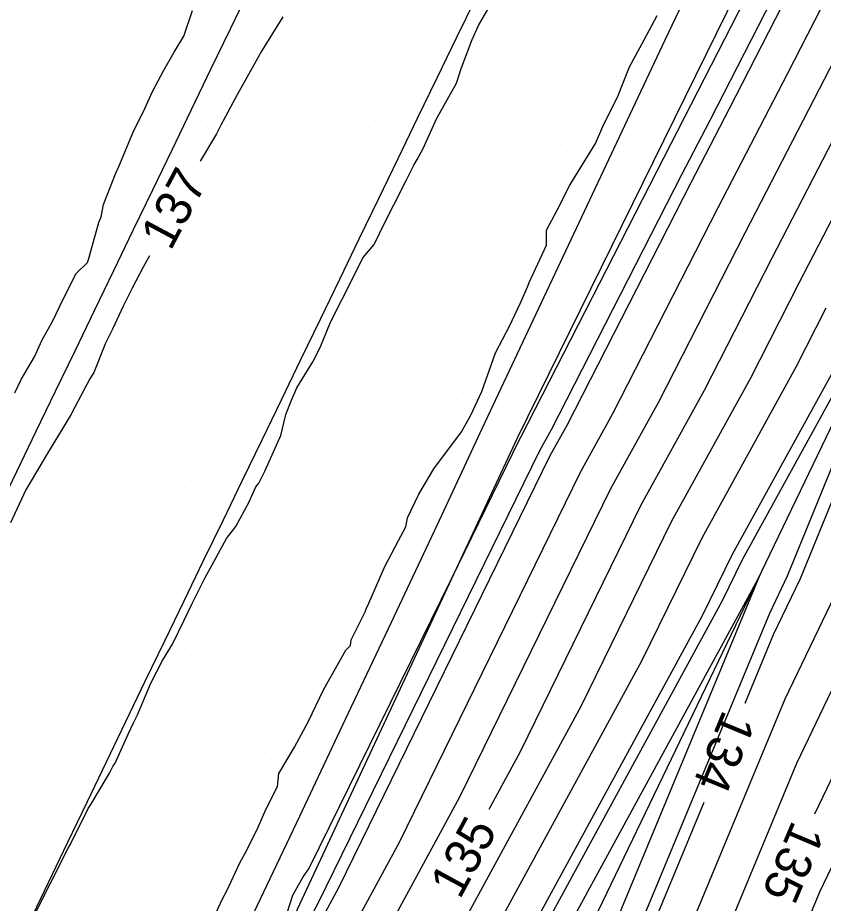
# Model space of a CAD drawing. Extents: x 2354170 to 2357230, y 866100 to 868290.
# Drawn here: x 2355293.68 to 2355338.78, y 866360.82 to 866410.37 of the extents above; entities that cross this region are included whole.
import ezdxf

# ---------------------------------------------------------------- set-up
doc = ezdxf.new("R2010")
doc.units = 0
for name, color, linetype in [('Default', 7, 'Continuous'), ('DTM Contours Major', 7, 'Continuous'), ('DTM Contours Major Text', 7, 'Continuous'), ('DTM Contours Minor', 7, 'Continuous'), ('DTM Contours Minor Text', 7, 'Continuous'), ('Exist DTM Breakline', 7, 'Continuous'), ('Exist DTM Scan Elevation Point', 7, 'Continuous'), ('Exist Roads EOP', 7, 'Continuous'), ('PH Exist DTM Breakline', 7, 'Continuous')]:
    doc.layers.add(name, color=color, linetype=linetype)

msp = doc.modelspace()

# ---------------------------------------------------------------- linework, layer by layer
at = {"layer": 'Default'}
for points in [[(2355334.401, 866372.018), (2355335.993, 866375.854), (2355337.498, 866378.987), (2355342.253, 866390.626), (2355343.246, 866392.695), (2355356.16, 866417.149), (2355356.262, 866417.357), (2355362.221, 866428.642), (2355363.371, 866431), (2355375.289, 866455.784), (2355376.359, 866457.979), (2355378.218, 866461.844)], [(2355338.298, 866365.818), (2355343.993, 866377.674), (2355346.753, 866384.429), (2355352.692, 866396.81), (2355360.315, 866411.244), (2355360.872, 866412.387), (2355364.386, 866419.041), (2355370.481, 866431.549), (2355377.431, 866446.002), (2355382.14, 866455.663)], [(2355365.278, 866455.25), (2355363.145, 866450.833), (2355355.882, 866436.056), (2355353.134, 866430.365), (2355349.614, 866423.554), (2355343.286, 866411.203), (2355335.903, 866396.918), (2355332.11, 866389.513), (2355328.572, 866383.089), (2355321.813, 866369.29), (2355320.06, 866366.07)], [(2355362.019, 866434.7), (2355360.618, 866431.85), (2355360.1, 866430.777), (2355354.214, 866419.388), (2355353.064, 866417.142), (2355340.439, 866392.713), (2355339.805, 866391.476), (2355333.667, 866380.332), (2355331.988, 866376.904), (2355319.48, 866353.942), (2355315.349, 866346.27)], [(2355308.598, 866359.764), (2355309.085, 866361.27), (2355309.657, 866362.299), (2355309.98, 866362.752), (2355317.96, 866378.969), (2355321.778, 866386.765), (2355321.85, 866386.896), (2355329.855, 866402.524), (2355330.249, 866403.286), (2355343.48, 866429.109)], [(2355344.863, 866427.426), (2355333.508, 866405.265), (2355331.367, 866401.122), (2355324.415, 866387.55), (2355323.476, 866385.846), (2355311.639, 866361.675), (2355310.176, 866358.99), (2355309.668, 866358.047), (2355299.946, 866338.09)], [(2355346.547, 866426.331), (2355336.768, 866407.245), (2355332.879, 866399.721), (2355326.98, 866388.205), (2355325.175, 866384.927), (2355315.03, 866364.214), (2355311.726, 866358.149), (2355310.58, 866356.02), (2355301.98, 866338.364), (2355299.636, 866333.974), (2355288.647, 866311.443), (2355286.904, 866307.449), (2355279.659, 866292.572), (2355279.343, 866291.067), (2355277.379, 866286.427), (2355269.582, 866267.361)], [(2355346.545, 866413.183), (2355337.415, 866395.516), (2355334.675, 866390.167), (2355330.27, 866382.17), (2355325.205, 866371.828), (2355316.378, 866355.625), (2355313.316, 866349.936), (2355308.274, 866339.587), (2355301.426, 866326.76), (2355294.428, 866312.41), (2355289.665, 866301.5), (2355285.05, 866292.025), (2355284.22, 866288.074), (2355279.066, 866275.895)], [(2355294.374, 866359.67), (2355295.392, 866361.693), (2355295.504, 866361.898), (2355296.511, 866363.894), (2355296.633, 866364.125), (2355297.628, 866366.123), (2355297.78, 866366.343), (2355298.816, 866368.103), (2355299.029, 866368.505), (2355299.143, 866368.656), (2355299.861, 866370.272), (2355300.162, 866370.917), (2355300.381, 866371.358), (2355301.13, 866373.134), (2355301.79, 866374.396), (2355302.344, 866375.317), (2355303.004, 866376.664), (2355303.437, 866377.546), (2355304.185, 866379.056), (2355304.573, 866379.763), (2355305.375, 866381.228), (2355305.901, 866381.896), (2355306.612, 866383.249), (2355307.008, 866384.127), (2355307.173, 866384.327), (2355307.513, 866385.005), (2355308.249, 866386.613), (2355308.412, 866386.992), (2355308.701, 866388.165), (2355309.011, 866388.966), (2355309.317, 866389.651), (2355310.198, 866391.115), (2355310.608, 866391.924), (2355311.193, 866393.331), (2355311.825, 866394.578), (2355312.303, 866395.542), (2355313.006, 866396.927), (2355313.629, 866397.687), (2355314.258, 866398.939), (2355314.744, 866399.903), (2355315.423, 866401.255), (2355315.853, 866402.126), (2355316.039, 866402.442), (2355316.386, 866403.048), (2355317.13, 866404.718), (2355318.242, 866406.714), (2355318.322, 866406.927), (2355318.482, 866407.479), (2355319.114, 866409.148), (2355319.475, 866409.933), (2355320.277, 866411.31)], [(2355304.299, 866359.25), (2355305.15, 866361.071), (2355305.394, 866361.523), (2355306.122, 866363.073), (2355306.501, 866363.789), (2355307.139, 866365.084), (2355307.576, 866366.075), (2355308.219, 866367.347), (2355308.292, 866368.085), (2355309.184, 866369.551), (2355309.941, 866370.98), (2355310.826, 866372.806), (2355312.05, 866374.99), (2355312.307, 866375.25), (2355312.345, 866375.55), (2355313.135, 866377.13), (2355313.209, 866377.336), (2355313.346, 866377.603), (2355314.23, 866379.658), (2355315, 866381.118), (2355315.41, 866381.875), (2355315.511, 866382.39), (2355316.142, 866383.704), (2355316.969, 866385.118), (2355318.531, 866387.205), (2355319.046, 866388.125), (2355319.659, 866389.453), (2355320.433, 866391.623), (2355321.216, 866393.109), (2355321.829, 866394.415), (2355322.23, 866395.349), (2355322.319, 866395.551), (2355323.286, 866397.648), (2355323.274, 866398.489), (2355323.881, 866399.608), (2355324.586, 866400.992), (2355326.024, 866403.328), (2355326.495, 866404.411), (2355327.25, 866405.927), (2355327.928, 866407.61), (2355328.749, 866409.137), (2355329.472, 866410.499)], [(2355340.027, 866409.224), (2355334.391, 866398.319), (2355329.545, 866388.859), (2355326.873, 866384.008), (2355318.422, 866366.752), (2355313.277, 866357.307), (2355311.492, 866353.992), (2355304.078, 866338.772), (2355300.233, 866331.569), (2355290.574, 866311.765), (2355287.824, 866305.466), (2355281.456, 866292.39), (2355280.968, 866290.07), (2355277.941, 866282.916), (2355271.317, 866266.718)], [(2355338.927, 866394.115), (2355337.24, 866390.821), (2355331.969, 866381.251), (2355328.597, 866374.366), (2355317.929, 866354.783), (2355314.227, 866347.909), (2355310.373, 866339.995), (2355302.023, 866324.355), (2355296.354, 866312.732), (2355290.585, 866299.517), (2355286.848, 866291.842), (2355285.846, 866287.077), (2355279.628, 866272.384)], [(2355307.474, 866311.114), (2355309.825, 866316.293), (2355318.648, 866338.833), (2355320.345, 866342.59), (2355324.053, 866352.236), (2355335.221, 866379.152), (2355321.03, 866353.1), (2355316.051, 866343.853), (2355314.569, 866340.81), (2355303.217, 866319.546), (2355300.208, 866313.377), (2355292.425, 866295.55), (2355290.442, 866291.477), (2355289.097, 866285.082), (2355280.753, 866265.362)], [(2355295.93, 866277.918), (2355297.289, 866281.095), (2355299.682, 866284.596), (2355304.457, 866295.671), (2355310.044, 866308.469), (2355314.474, 866318.226), (2355320.982, 866334.853), (2355325.394, 866344.623), (2355328.175, 866351.855), (2355336.64, 866372.256), (2355339.663, 866378.549)], [(2355297.265, 866276.227), (2355299.022, 866280.337), (2355300.896, 866283.079), (2355306.792, 866296.752), (2355311.329, 866307.146), (2355316.798, 866319.192), (2355322.15, 866332.863), (2355327.919, 866345.64), (2355330.235, 866351.664), (2355337.287, 866368.659), (2355341.828, 866378.112)], [(2355299.933, 866272.846), (2355302.488, 866278.82), (2355303.324, 866280.044), (2355311.461, 866298.914), (2355313.9, 866304.5), (2355321.447, 866321.125), (2355324.484, 866328.882), (2355332.969, 866347.673), (2355334.356, 866351.282), (2355338.581, 866361.464), (2355346.158, 866377.236)], [(2355291.94, 866275.064), (2355294.596, 866279.608), (2355295.556, 866281.853), (2355298.468, 866286.114), (2355302.123, 866294.59), (2355308.759, 866309.791), (2355312.149, 866317.259), (2355319.815, 866336.843), (2355322.869, 866343.607), (2355326.114, 866352.046), (2355332.101, 866366.476)]]:
    msp.add_lwpolyline(points, dxfattribs=at)
at = {"layer": 'DTM Contours Major'}
for points in [[(2355338.298, 866365.818), (2355343.993, 866377.674), (2355346.753, 866384.429), (2355352.692, 866396.81), (2355360.315, 866411.244), (2355360.872, 866412.387), (2355364.386, 866419.041), (2355370.481, 866431.549), (2355377.431, 866446.002), (2355382.14, 866455.663)], [(2355365.278, 866455.25), (2355363.145, 866450.833), (2355355.882, 866436.056), (2355353.134, 866430.365), (2355349.614, 866423.554), (2355343.286, 866411.203), (2355335.903, 866396.918), (2355332.11, 866389.513), (2355328.572, 866383.089), (2355321.813, 866369.29), (2355320.06, 866366.07)]]:
    msp.add_lwpolyline(points, dxfattribs=at)
at = {"layer": 'DTM Contours Minor'}
for points in [[(2355399.763, 866516.766), (2355393.392, 866501.457), (2355392.787, 866500.397), (2355391.502, 866497.306), (2355381.19, 866472.262), (2355380.988, 866471.775), (2355374.355, 866458.281), (2355373.867, 866457.271), (2355361.144, 866431.383), (2355360.874, 866430.823), (2355354.726, 866418.925), (2355354.15, 866417.801), (2355340.943, 866392.246), (2355340.66, 866391.694), (2355334.233, 866380.026), (2355333.119, 866377.75), (2355319.997, 866353.661), (2355315.443, 866345.205), (2355313.17, 866340.539), (2355311.526, 866337.459)], [(2355308.331, 866310.232), (2355311.374, 866316.937), (2355319.426, 866337.506), (2355322.028, 866343.268), (2355325.427, 866352.109), (2355335.777, 866377.053), (2355336.776, 866379.133), (2355341.753, 866391.314), (2355342.196, 866392.238), (2355355.699, 866417.805), (2355355.75, 866417.909), (2355361.981, 866429.708), (2355362.581, 866430.939), (2355375.051, 866456.87), (2355375.559, 866457.912), (2355382.058, 866471.427), (2355382.481, 866472.365), (2355392.371, 866491.519)], [(2355267.268, 866268.217), (2355276.63, 866291.108), (2355277.175, 866292.398), (2355277.263, 866292.816), (2355285.677, 866310.094), (2355286.078, 866311.013), (2355298.84, 866337.18), (2355299.182, 866337.821), (2355309.364, 866358.723), (2355309.659, 866359.271), (2355310.508, 866360.829), (2355322.91, 866386.152), (2355323.56, 866387.332), (2355330.863, 866401.589), (2355332.422, 866404.606), (2355337.089, 866413.714)], [(2355293.531, 866389.374), (2355293.872, 866390.129), (2355294.621, 866391.4), (2355295.047, 866392.35), (2355295.647, 866393.413), (2355296.201, 866394.584), (2355296.959, 866396.058), (2355297.588, 866396.664), (2355297.645, 866396.841), (2355298.231, 866398.901), (2355298.349, 866399.221), (2355298.495, 866399.923), (2355299.153, 866401.624), (2355299.349, 866402.042), (2355300.148, 866403.963), (2355300.806, 866405.288), (2355301.23, 866406.245), (2355301.86, 866407.426), (2355302.433, 866408.446), (2355302.979, 866409.338), (2355303.46, 866410.764)], [(2355308.518, 866410.416), (2355307.277, 866408.409), (2355307.21, 866408.284), (2355307.129, 866408.13), (2355305.995, 866406.089), (2355305.061, 866404.35), (2355304.81, 866403.876), (2355303.891, 866402.338)], [(2355301.065, 866397.048), (2355300.712, 866396.403), (2355300.098, 866395.24), (2355299.602, 866394.259), (2355298.985, 866392.939), (2355298.602, 866392.164), (2355297.945, 866390.522), (2355297.724, 866390.165), (2355296.722, 866388.262), (2355296.676, 866388.188), (2355296.234, 866387.445), (2355295.445, 866386.155), (2355295.418, 866386.109), (2355295.388, 866386.054), (2355294.137, 866383.959), (2355293.278, 866382.106)]]:
    msp.add_lwpolyline(points, dxfattribs=at)
at = {"layer": 'Exist DTM Breakline'}
for points in [[(2355281.733, 866360.182), (2355282.807, 866362.44), (2355283.88, 866364.698), (2355284.954, 866366.955), (2355286.027, 866369.213), (2355287.104, 866371.469), (2355288.192, 866373.72), (2355289.279, 866375.971), (2355290.367, 866378.223), (2355291.454, 866380.474), (2355292.542, 866382.725), (2355293.629, 866384.976), (2355294.717, 866387.227), (2355295.804, 866389.478), (2355296.892, 866391.729), (2355297.979, 866393.98), (2355299.067, 866396.231), (2355300.154, 866398.482), (2355301.242, 866400.733), (2355302.329, 866402.984), (2355303.416, 866405.236), (2355304.501, 866407.488), (2355305.586, 866409.74), (2355306.671, 866411.993)], [(2355319.318, 866411.481), (2355318.23, 866409.23), (2355317.141, 866406.979), (2355316.052, 866404.729), (2355314.963, 866402.479), (2355313.874, 866400.228), (2355312.785, 866397.978), (2355311.696, 866395.728), (2355310.607, 866393.477), (2355309.518, 866391.227), (2355308.43, 866388.976), (2355307.342, 866386.725), (2355306.253, 866384.475), (2355305.164, 866382.225), (2355304.073, 866379.975), (2355302.982, 866377.726), (2355301.892, 866375.476), (2355300.806, 866373.224), (2355299.723, 866370.971), (2355298.64, 866368.718), (2355297.557, 866366.465), (2355296.471, 866364.212), (2355295.385, 866361.961), (2355294.298, 866359.709)]]:
    msp.add_lwpolyline(points, dxfattribs=at)
at = {"layer": 'Exist DTM Scan Elevation Point'}
for p, q in [((2355295.981, 866409.717), (2355295.981, 866409.717)), ((2355304.995, 866409.749), (2355304.995, 866409.749)), ((2355314.009, 866409.781), (2355314.009, 866409.781)), ((2355323.023, 866409.812), (2355323.023, 866409.812)), ((2355301.531, 866409.043), (2355301.531, 866409.043)), ((2355310.545, 866409.075), (2355310.545, 866409.075)), ((2355319.558, 866409.107), (2355319.558, 866409.107)), ((2355328.572, 866409.138), (2355328.572, 866409.138)), ((2355298.066, 866408.338), (2355298.066, 866408.338)), ((2355307.08, 866408.369), (2355307.08, 866408.369)), ((2355316.094, 866408.401), (2355316.094, 866408.401)), ((2355325.108, 866408.433), (2355325.108, 866408.433)), ((2355294.602, 866407.632), (2355294.602, 866407.632)), ((2355303.616, 866407.664), (2355303.616, 866407.664)), ((2355312.63, 866407.696), (2355312.63, 866407.696)), ((2355321.643, 866407.727), (2355321.643, 866407.727)), ((2355300.151, 866406.958), (2355300.151, 866406.958)), ((2355309.165, 866406.99), (2355309.165, 866406.99)), ((2355318.179, 866407.022), (2355318.179, 866407.022)), ((2355327.193, 866407.053), (2355327.193, 866407.053)), ((2355296.687, 866406.253), (2355296.687, 866406.253)), ((2355305.701, 866406.284), (2355305.701, 866406.284)), ((2355314.715, 866406.316), (2355314.715, 866406.316)), ((2355323.728, 866406.348), (2355323.728, 866406.348)), ((2355302.236, 866405.579), (2355302.236, 866405.579)), ((2355311.25, 866405.611), (2355311.25, 866405.611)), ((2355320.264, 866405.642), (2355320.264, 866405.642)), ((2355325.813, 866404.968), (2355325.813, 866404.968)), ((2355298.772, 866404.873), (2355298.772, 866404.873)), ((2355307.786, 866404.905), (2355307.786, 866404.905)), ((2355316.8, 866404.937), (2355316.8, 866404.937)), ((2355295.307, 866404.168), (2355295.307, 866404.168)), ((2355304.321, 866404.2), (2355304.321, 866404.2)), ((2355313.335, 866404.231), (2355313.335, 866404.231)), ((2355322.349, 866404.263), (2355322.349, 866404.263)), ((2355300.857, 866403.494), (2355300.857, 866403.494)), ((2355309.871, 866403.526), (2355309.871, 866403.526)), ((2355318.885, 866403.557), (2355318.885, 866403.557)), ((2355297.392, 866402.788), (2355297.392, 866402.788)), ((2355306.406, 866402.82), (2355306.406, 866402.82)), ((2355315.42, 866402.852), (2355315.42, 866402.852)), ((2355324.434, 866402.883), (2355324.434, 866402.883)), ((2355293.928, 866402.083), (2355293.928, 866402.083)), ((2355302.942, 866402.115), (2355302.942, 866402.115)), ((2355311.956, 866402.146), (2355311.956, 866402.146)), ((2355320.97, 866402.178), (2355320.97, 866402.178)), ((2355299.477, 866401.409), (2355299.477, 866401.409)), ((2355308.491, 866401.441), (2355308.491, 866401.441)), ((2355317.505, 866401.472), (2355317.505, 866401.472)), ((2355296.013, 866400.703), (2355296.013, 866400.703)), ((2355305.027, 866400.735), (2355305.027, 866400.735)), ((2355314.041, 866400.767), (2355314.041, 866400.767)), ((2355323.055, 866400.798), (2355323.055, 866400.798)), ((2355301.562, 866400.03), (2355301.562, 866400.03)), ((2355310.576, 866400.061), (2355310.576, 866400.061)), ((2355319.59, 866400.093), (2355319.59, 866400.093)), ((2355298.098, 866399.324), (2355298.098, 866399.324)), ((2355307.112, 866399.356), (2355307.112, 866399.356)), ((2355316.126, 866399.387), (2355316.126, 866399.387)), ((2355294.634, 866398.618), (2355294.634, 866398.618)), ((2355303.647, 866398.65), (2355303.647, 866398.65)), ((2355312.661, 866398.682), (2355312.661, 866398.682)), ((2355321.675, 866398.713), (2355321.675, 866398.713)), ((2355300.183, 866397.945), (2355300.183, 866397.945)), ((2355309.197, 866397.976), (2355309.197, 866397.976)), ((2355318.211, 866398.008), (2355318.211, 866398.008)), ((2355296.719, 866397.239), (2355296.719, 866397.239)), ((2355305.732, 866397.271), (2355305.732, 866397.271)), ((2355314.746, 866397.302), (2355314.746, 866397.302)), ((2355323.76, 866397.334), (2355323.76, 866397.334)), ((2355302.268, 866396.565), (2355302.268, 866396.565)), ((2355311.282, 866396.597), (2355311.282, 866396.597)), ((2355320.296, 866396.628), (2355320.296, 866396.628)), ((2355298.804, 866395.86), (2355298.804, 866395.86)), ((2355307.817, 866395.891), (2355307.817, 866395.891)), ((2355316.831, 866395.923), (2355316.831, 866395.923)), ((2355295.339, 866395.154), (2355295.339, 866395.154)), ((2355304.353, 866395.186), (2355304.353, 866395.186)), ((2355313.367, 866395.217), (2355313.367, 866395.217)), ((2355322.381, 866395.249), (2355322.381, 866395.249)), ((2355300.889, 866394.48), (2355300.889, 866394.48)), ((2355309.902, 866394.512), (2355309.902, 866394.512)), ((2355318.916, 866394.543), (2355318.916, 866394.543)), ((2355297.424, 866393.775), (2355297.424, 866393.775)), ((2355306.438, 866393.806), (2355306.438, 866393.806)), ((2355315.452, 866393.838), (2355315.452, 866393.838)), ((2355302.974, 866393.101), (2355302.974, 866393.101)), ((2355311.987, 866393.132), (2355311.987, 866393.132)), ((2355321.001, 866393.164), (2355321.001, 866393.164)), ((2355293.96, 866393.069), (2355293.96, 866393.069)), ((2355299.509, 866392.395), (2355299.509, 866392.395)), ((2355308.523, 866392.427), (2355308.523, 866392.427)), ((2355317.537, 866392.458), (2355317.537, 866392.458)), ((2355296.045, 866391.69), (2355296.045, 866391.69)), ((2355305.059, 866391.721), (2355305.059, 866391.721)), ((2355314.072, 866391.753), (2355314.072, 866391.753)), ((2355301.594, 866391.016), (2355301.594, 866391.016)), ((2355310.608, 866391.047), (2355310.608, 866391.047)), ((2355319.622, 866391.079), (2355319.622, 866391.079)), ((2355298.13, 866390.31), (2355298.13, 866390.31)), ((2355307.144, 866390.342), (2355307.144, 866390.342)), ((2355316.157, 866390.374), (2355316.157, 866390.374)), ((2355303.679, 866389.636), (2355303.679, 866389.636)), ((2355312.693, 866389.668), (2355312.693, 866389.668)), ((2355294.665, 866389.605), (2355294.665, 866389.605)), ((2355300.215, 866388.931), (2355300.215, 866388.931)), ((2355309.229, 866388.962), (2355309.229, 866388.962)), ((2355318.242, 866388.994), (2355318.242, 866388.994)), ((2355296.75, 866388.225), (2355296.75, 866388.225)), ((2355305.764, 866388.257), (2355305.764, 866388.257)), ((2355314.778, 866388.289), (2355314.778, 866388.289)), ((2355302.3, 866387.551), (2355302.3, 866387.551)), ((2355311.314, 866387.583), (2355311.314, 866387.583)), ((2355298.835, 866386.846), (2355298.835, 866386.846)), ((2355307.849, 866386.877), (2355307.849, 866386.877)), ((2355316.863, 866386.909), (2355316.863, 866386.909)), ((2355295.371, 866386.14), (2355295.371, 866386.14)), ((2355304.385, 866386.172), (2355304.385, 866386.172)), ((2355313.398, 866386.204), (2355313.398, 866386.204)), ((2355300.92, 866385.466), (2355300.92, 866385.466)), ((2355309.934, 866385.498), (2355309.934, 866385.498)), ((2355297.456, 866384.761), (2355297.456, 866384.761)), ((2355306.47, 866384.792), (2355306.47, 866384.792)), ((2355315.483, 866384.824), (2355315.483, 866384.824)), ((2355293.991, 866384.055), (2355293.991, 866384.055)), ((2355303.005, 866384.087), (2355303.005, 866384.087)), ((2355312.019, 866384.119), (2355312.019, 866384.119)), ((2355299.541, 866383.381), (2355299.541, 866383.381)), ((2355308.555, 866383.413), (2355308.555, 866383.413)), ((2355296.076, 866382.676), (2355296.076, 866382.676)), ((2355305.09, 866382.707), (2355305.09, 866382.707)), ((2355314.104, 866382.739), (2355314.104, 866382.739)), ((2355301.626, 866382.002), (2355301.626, 866382.002)), ((2355310.64, 866382.034), (2355310.64, 866382.034)), ((2355298.161, 866381.296), (2355298.161, 866381.296)), ((2355307.175, 866381.328), (2355307.175, 866381.328)), ((2355316.189, 866381.36), (2355316.189, 866381.36)), ((2355294.697, 866380.591), (2355294.697, 866380.591)), ((2355303.711, 866380.622), (2355303.711, 866380.622)), ((2355312.725, 866380.654), (2355312.725, 866380.654)), ((2355300.246, 866379.917), (2355300.246, 866379.917)), ((2355309.26, 866379.949), (2355309.26, 866379.949)), ((2355296.782, 866379.211), (2355296.782, 866379.211)), ((2355305.796, 866379.243), (2355305.796, 866379.243)), ((2355314.81, 866379.275), (2355314.81, 866379.275)), ((2355302.331, 866378.537), (2355302.331, 866378.537)), ((2355311.345, 866378.569), (2355311.345, 866378.569)), ((2355298.867, 866377.832), (2355298.867, 866377.832)), ((2355307.881, 866377.864), (2355307.881, 866377.864)), ((2355295.403, 866377.126), (2355295.403, 866377.126)), ((2355304.416, 866377.158), (2355304.416, 866377.158)), ((2355313.43, 866377.19), (2355313.43, 866377.19)), ((2355300.952, 866376.452), (2355300.952, 866376.452)), ((2355309.966, 866376.484), (2355309.966, 866376.484)), ((2355297.488, 866375.747), (2355297.488, 866375.747)), ((2355306.501, 866375.779), (2355306.501, 866375.779)), ((2355294.023, 866375.041), (2355294.023, 866375.041)), ((2355303.037, 866375.073), (2355303.037, 866375.073)), ((2355312.051, 866375.105), (2355312.051, 866375.105)), ((2355299.572, 866374.367), (2355299.572, 866374.367)), ((2355308.586, 866374.399), (2355308.586, 866374.399)), ((2355296.108, 866373.662), (2355296.108, 866373.662)), ((2355305.122, 866373.694), (2355305.122, 866373.694)), ((2355301.657, 866372.988), (2355301.657, 866372.988)), ((2355310.671, 866373.02), (2355310.671, 866373.02)), ((2355298.193, 866372.283), (2355298.193, 866372.283)), ((2355307.207, 866372.314), (2355307.207, 866372.314)), ((2355294.729, 866371.577), (2355294.729, 866371.577)), ((2355303.742, 866371.609), (2355303.742, 866371.609)), ((2355300.278, 866370.903), (2355300.278, 866370.903)), ((2355309.292, 866370.935), (2355309.292, 866370.935)), ((2355296.814, 866370.198), (2355296.814, 866370.198)), ((2355305.827, 866370.229), (2355305.827, 866370.229)), ((2355302.363, 866369.524), (2355302.363, 866369.524)), ((2355298.899, 866368.818), (2355298.899, 866368.818)), ((2355307.912, 866368.85), (2355307.912, 866368.85)), ((2355295.434, 866368.113), (2355295.434, 866368.113)), ((2355304.448, 866368.144), (2355304.448, 866368.144)), ((2355300.984, 866367.439), (2355300.984, 866367.439)), ((2355297.519, 866366.733), (2355297.519, 866366.733)), ((2355306.533, 866366.765), (2355306.533, 866366.765)), ((2355294.055, 866366.028), (2355294.055, 866366.028)), ((2355303.069, 866366.059), (2355303.069, 866366.059)), ((2355299.604, 866365.354), (2355299.604, 866365.354)), ((2355308.618, 866365.385), (2355308.618, 866365.385)), ((2355296.14, 866364.648), (2355296.14, 866364.648)), ((2355305.154, 866364.68), (2355305.154, 866364.68)), ((2355301.689, 866363.974), (2355301.689, 866363.974)), ((2355298.225, 866363.269), (2355298.225, 866363.269)), ((2355307.239, 866363.3), (2355307.239, 866363.3)), ((2355294.76, 866362.563), (2355294.76, 866362.563)), ((2355303.774, 866362.595), (2355303.774, 866362.595)), ((2355300.31, 866361.889), (2355300.31, 866361.889)), ((2355296.845, 866361.184), (2355296.845, 866361.184)), ((2355305.859, 866361.215), (2355305.859, 866361.215))]:
    msp.add_line(p, q, dxfattribs=at)
at = {"layer": 'Exist Roads EOP'}
msp.add_lwpolyline([(2355306.905, 866360.281), (2355309.475, 866365.702), (2355312.04, 866371.126), (2355314.6, 866376.553), (2355317.155, 866381.982), (2355319.705, 866387.413), (2355322.254, 866392.844), (2355324.805, 866398.275), (2355327.362, 866403.703), (2355329.928, 866409.126), (2355332.504, 866414.545), (2355335.088, 866419.96), (2355337.679, 866425.372), (2355340.273, 866430.782)], dxfattribs=at)
at = {"layer": 'PH Exist DTM Breakline'}
for points in [[(2355462.264, 866681.282), (2355449.29, 866652.845), (2355431.772, 866616.884), (2355416.85, 866585.734), (2355398.908, 866547.275), (2355381.513, 866510.255), (2355362.049, 866469.228), (2355342.769, 866429.753), (2355321.636, 866386.842), (2355298.704, 866337.728), (2355276.341, 866292.909), (2355263.024, 866269.789)], [(2355281.117, 866263.09), (2355291.385, 866283.678), (2355294.507, 866291.064), (2355304.567, 866314.107), (2355322.328, 866352.396), (2355341.35, 866391.869), (2355361.718, 866430.873), (2355381.648, 866471.864), (2355403.329, 866518.372), (2355424.612, 866562.24), (2355423.403, 866563.319), (2355423.174, 866564.881), (2355424.474, 866567.914), (2355426.326, 866567.421), (2355427.666, 866565.955), (2355427.962, 866564.005), (2355426.4, 866561.553)]]:
    msp.add_lwpolyline(points, dxfattribs=at)

# ---------------------------------------------------------------- texts
at = {"layer": 'Default'}
for s, rotation, p in [('134', 247.4648, (2355333.188, 866371.703)), ('135', 61.4212, (2355318.429, 866360.987)), ('135', 247.0275, (2355337.061, 866365.523))]:
    msp.add_text(s, height=2, rotation=rotation, dxfattribs=at).set_placement(p)
at = {"layer": 'DTM Contours Major Text'}
for rotation, p in [(61.4212, (2355318.429, 866360.987)), (247.0275, (2355337.061, 866365.523))]:
    msp.add_text('135', height=2, rotation=rotation, dxfattribs=at).set_placement(p)
at = {"layer": 'DTM Contours Minor Text'}
msp.add_text('137', height=2, rotation=61.8862, dxfattribs=at).set_placement((2355302.24, 866397.276))

doc.saveas('drawing.dxf')
